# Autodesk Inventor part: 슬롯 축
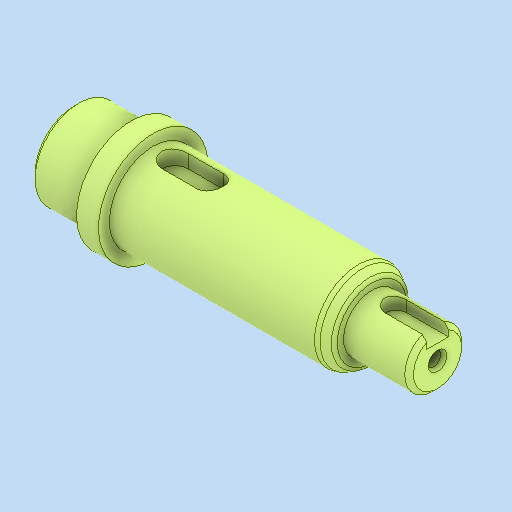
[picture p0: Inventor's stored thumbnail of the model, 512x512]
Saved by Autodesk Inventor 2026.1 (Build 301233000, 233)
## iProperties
Created: 2025-09
Part Number: 슬롯 축
Material: 강철, 탄소
Document SubType Name: Modeling
Designer: PC-30
Density: 7.85 g/cm^3
Appearance: 기본값
Author: jhkim
Sending System: Autodesk Inventor 2026
Preprocessor: ST-DEVELOPER v20.1
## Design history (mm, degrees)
feature "솔리드1"
node "솔리드2"
